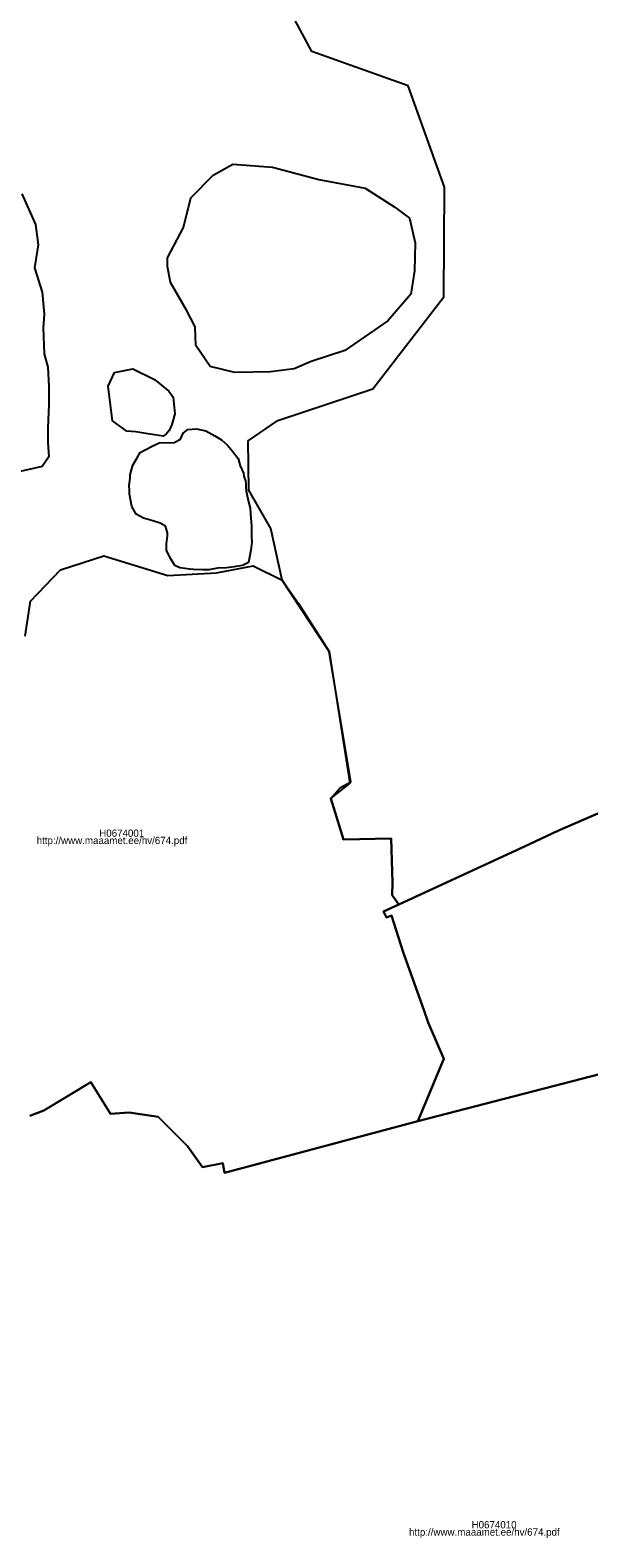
# Model space of a CAD drawing. Extents: x 369010 to 739155, y 6377141 to 6634081.
# Drawn here: x 475318 to 477233, y 6531772 to 6536944 of the extents above; entities that cross this region are included whole.
import ezdxf

# ---------------------------------------------------------------- set-up
doc = ezdxf.new("R2010")
doc.units = 0
for name, color, linetype in [('H_LINK', 7, 'Continuous'), ('H_PIIR', 7, 'Continuous'), ('H_TUNNUS', 7, 'Continuous')]:
    doc.layers.add(name, color=color, linetype=linetype)

msp = doc.modelspace()

# ---------------------------------------------------------------- linework, layer by layer
at = {"layer": 'H_PIIR'}
for points in [[(477281.93, 6534264.91), (477127.03, 6534196.6299), (477013.1099, 6534142.9699), (476581.4999, 6533944.28), (476559.0799, 6533976.07), (476560.48, 6534020.02), (476555.7201, 6534170.51), (476392.48, 6534167.9701), (476348.24, 6534308.3), (476348.1743, 6534308.7202), (476354.8099, 6534314.7), (476381.2699, 6534345.5801), (476417.43, 6534365.43), (476342.48, 6534812.63), (476182.1413, 6535056.4606), (476143.512, 6535234.7901), (476067.3119, 6535366.0237), (476065.1952, 6535535.3574), (476166.7954, 6535605.2075), (476492.7627, 6535713.1577), (476736.1799, 6536028.5417), (476738.2965, 6536405.3091), (476613.413, 6536752.4431), (476283.2123, 6536870.9767), (476141.3954, 6537135.5606)], [(475289.5676, 6536382.8195), (475335.8698, 6536276.9859), (475345.7917, 6536207.5327), (475332.5625, 6536128.1575), (475359.0209, 6536045.475), (475365.6355, 6535969.4072), (475362.3282, 6535923.105), (475365.6355, 6535833.808), (475378.8647, 6535787.5058), (475382.172, 6535721.3598), (475382.172, 6535658.5212), (475378.8647, 6535579.146), (475378.8647, 6535529.5365), (475382.172, 6535479.927), (475359.0209, 6535446.8541), (475273.0311, 6535427.0103)], [(475300.8124, 6534864.3727), (475319.3333, 6534984.7583), (475421.9918, 6535092.7086), (475569.8942, 6535140.5982), (475790.028, 6535072.8648), (475956.7158, 6535081.8606), (476082.1286, 6535105.6732), (476182.1413, 6535056.4606), (476237.7039, 6534977.0854), (476342.48, 6534812.63), (476413.62, 6534360.57), (476348.1743, 6534308.7202), (476348.24, 6534308.3), (476392.48, 6534167.9701), (476555.7201, 6534170.51), (476560.48, 6534020.02), (476559.0799, 6533976.07), (476581.4999, 6533944.28), (476529.7401, 6533920.19), (476539.17, 6533899.35), (476556.42, 6533906.68), (476596.6501, 6533780.6699), (476666.9799, 6533583.4701), (476681.9699, 6533539.82), (476735.5599, 6533414.5), (476646.63, 6533201), (475983.8601, 6533024.1799), (475978.93, 6533057.04), (475908.8701, 6533044.0001), (475857.29, 6533115.3499), (475756.9899, 6533216.01), (475657.15, 6533231.3799), (475593.48, 6533226.5), (475525.8301, 6533335.08), (475364.8401, 6533237.45), (475316.2799, 6533219.06)], [(480416.2601, 6534176.91), (476646.63, 6533201), (476735.5599, 6533414.5), (476681.9699, 6533539.82), (476666.9799, 6533583.4701), (476596.6501, 6533780.6699), (476556.42, 6533906.68), (476539.17, 6533899.35), (476529.7401, 6533920.19), (476581.4999, 6533944.28), (477013.1099, 6534142.9699), (477127.03, 6534196.6299), (477281.93, 6534264.91)], [(475316.2799, 6533219.06), (475364.8401, 6533237.45), (475525.8301, 6533335.08), (475593.48, 6533226.5), (475657.15, 6533231.3799), (475756.9899, 6533216.01), (475857.29, 6533115.3499), (475908.8701, 6533044.0001), (475978.93, 6533057.04), (475983.8601, 6533024.1799), (476646.63, 6533201), (480416.2601, 6534176.91)]]:
    msp.add_lwpolyline(points, dxfattribs=at)
for points in [[(475843.6503, 6536266.5349), (475869.0504, 6536368.1351), (475945.2505, 6536446.4519), (476012.984, 6536484.552), (476148.4509, 6536473.9686), (476307.2012, 6536431.6352), (476465.9516, 6536402.0018), (476567.5518, 6536336.385), (476618.3519, 6536298.2849), (476637.4019, 6536213.6181), (476635.2852, 6536118.3679), (476622.5852, 6536037.9344), (476544.2684, 6535946.9176), (476396.1014, 6535845.3174), (476281.8012, 6535807.2173), (476222.5344, 6535781.8172), (476142.1009, 6535771.2339), (476019.334, 6535769.1172), (475934.6672, 6535790.2839), (475885.9837, 6535862.2507), (475883.8671, 6535925.7509), (475854.2337, 6535982.901), (475799.2002, 6536078.1512), (475788.6169, 6536133.1846), (475788.6169, 6536162.818)], [(475714.5334, 6535559.5668), (475680.6667, 6535565.9168), (475648.9166, 6535568.0335), (475600.2332, 6535604.0169), (475585.4165, 6535722.5504), (475606.5832, 6535769.1172), (475670.0833, 6535781.8172), (475744.1668, 6535745.8338), (475792.8502, 6535705.6171), (475807.6669, 6535684.4504), (475814.0169, 6535627.3003), (475803.4336, 6535591.3168), (475794.9669, 6535570.1501), (475784.3835, 6535557.4501), (475773.8002, 6535551.1001)], [(475735.9206, 6535516.5719), (475759.7331, 6535527.8167), (475811.9884, 6535529.8011), (475833.8166, 6535541.0459), (475842.4156, 6535560.8897), (475858.9521, 6535573.4574), (475888.0563, 6535576.1033), (475920.4678, 6535569.4887), (475950.895, 6535551.6293), (475973.3846, 6535538.4001), (475993.8898, 6535519.8792), (476011.7493, 6535499.374), (476030.9316, 6535474.9), (476037.5462, 6535449.7645), (476048.791, 6535423.9676), (476050.7754, 6535414.0457), (476056.0671, 6535397.5092), (476056.7285, 6535388.9102), (476056.7285, 6535376.3425), (476058.0514, 6535363.1133), (476061.3587, 6535346.5768), (476065.989, 6535325.4101), (476071.9421, 6535303.5819), (476074.5879, 6535269.8475), (476077.2338, 6535243.3891), (476077.2338, 6535207.6702), (476077.8952, 6535187.165), (476074.5879, 6535159.3837), (476066.6504, 6535117.7117), (476045.4837, 6535107.1284), (476017.0409, 6535103.1596), (475990.5825, 6535099.1909), (475960.1554, 6535097.8679), (475930.3897, 6535092.5763), (475909.223, 6535091.9148), (475877.4729, 6535093.2377), (475864.9052, 6535094.5606), (475831.1708, 6535099.8523), (475813.3114, 6535107.7898), (475798.0978, 6535133.5868), (475785.5301, 6535160.0452), (475784.8686, 6535181.8733), (475788.1759, 6535209.6546), (475788.1759, 6535218.9151), (475782.2228, 6535242.7276), (475763.7019, 6535252.6495), (475737.905, 6535260.587), (475706.1549, 6535269.186), (475681.0194, 6535283.7381), (475666.4673, 6535310.1965), (475658.5298, 6535351.8685), (475657.8683, 6535365.7591), (475657.2069, 6535382.2956), (475661.1756, 6535407.4311), (475661.1756, 6535418.6759), (475665.1444, 6535435.8738), (475669.7746, 6535451.0874), (475684.9882, 6535476.8843), (475694.9101, 6535495.4052)]]:
    msp.add_lwpolyline(points, close=True, dxfattribs=at)

# ---------------------------------------------------------------- texts
at = {"layer": 'H_LINK'}
msp.add_text('http://www.maaamet.ee/hv/674.pdf', height=25, rotation=0, dxfattribs=at).set_placement((475340.2186, 6534151.6902))
msp.add_text('http://www.maaamet.ee/hv/674.pdf', height=25, dxfattribs=at).set_placement((476616.7709, 6531779.4406))
at = {"layer": 'H_TUNNUS'}
msp.add_text('H0674001', height=25, rotation=0, dxfattribs=at).set_placement((475554.5725, 6534176.6902))
msp.add_text('H0674010', height=25, dxfattribs=at).set_placement((476831.1248, 6531804.4406))

doc.saveas('drawing.dxf')
